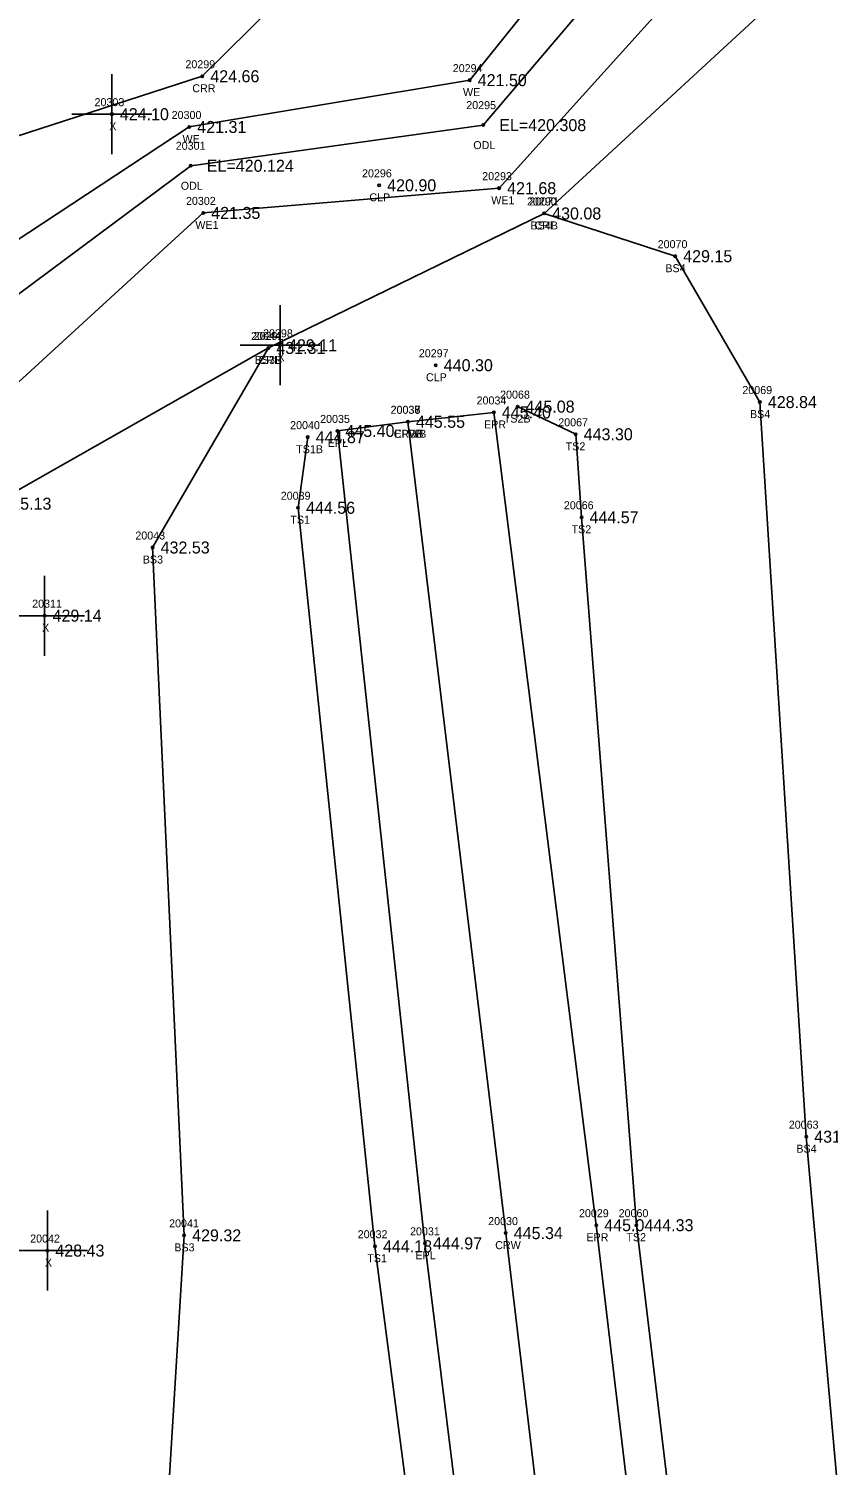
# Model space of a CAD drawing. Extents: x 1858461 to 1858936, y 1147060 to 1148183.
# Drawn here: x 1858641.9 to 1858741.9, y 1147440.4 to 1147619.9 of the extents above; entities that cross this region are included whole.
import ezdxf

# ---------------------------------------------------------------- set-up
doc = ezdxf.new("R2010")
doc.units = 0
for name, color, linetype in [('RD_DTM_BkLn1', 7, 'Continuous'), ('RD_DTM_BkLn2', 7, 'Continuous'), ('RD_DTM_BkLn_txCode', 7, 'Continuous'), ('RD_EX_H2O', 7, 'Continuous'), ('RD_EX_H2O_txCode', 7, 'Continuous'), ('RD_EX_Misc', 7, 'Continuous'), ('RD_EX_Misc_txCode', 7, 'Continuous'), ('RD_EX_Road', 7, 'Continuous'), ('RD_EX_Road_txCode', 7, 'Continuous'), ('RD_EX_TX_H2O_ELEV', 7, 'Continuous'), ('RD_EX_TX_Misc_ELEV', 7, 'Continuous'), ('RD_EX_TX_Road_ELEV', 7, 'Continuous'), ('RD_HC_Survey_ELEV', 7, 'Continuous'), ('RD_HC_Survey_txCode', 7, 'Continuous'), ('RD_SMD_Locator', 7, 'Continuous')]:
    doc.layers.add(name, color=color, linetype=linetype)

msp = doc.modelspace()

# ---------------------------------------------------------------- linework, layer by layer
at = {"layer": 'RD_DTM_BkLn1'}
msp.add_lwpolyline([(1858749.22, 1147073.22), (1858736.71, 1147171.73), (1858725.84, 1147271.15), (1858713.42, 1147369.59), (1858701.55, 1147469.39), (1858689.32, 1147570.79)], dxfattribs=at)
at = {"layer": 'RD_DTM_BkLn2'}
for points in [[(1858771.94, 1147076.95), (1858767.25, 1147173.88), (1858758.88, 1147274.75), (1858748.81, 1147373.06), (1858739.11, 1147481.44), (1858733.31, 1147573.26), (1858722.73, 1147591.49), (1858706.35, 1147596.83)], [(1858714.74, 1147067.6), (1858710.56, 1147167.02), (1858688.24, 1147264.23), (1858669.68, 1147349.51), (1858651.77, 1147379.27), (1858656.32, 1147386.54), (1858661.34, 1147469.11), (1858657.4, 1147555.08), (1858671.87, 1147580.02)], [(1858771.94, 1147076.95), (1858754.29, 1147172.99), (1858743.32, 1147272.09), (1858729.94, 1147370.14), (1858717.88, 1147470.38), (1858711.02, 1147558.86), (1858710.29, 1147569.23), (1858703.02, 1147572.69)], [(1858727.7, 1147071.22), (1858717.51, 1147168.6), (1858707.4, 1147267.83), (1858698.1, 1147368.78), (1858685.2, 1147467.75), (1858675.58, 1147560.05), (1858676.79, 1147568.87)]]:
    msp.add_lwpolyline(points, dxfattribs=at)
at = {"layer": 'RD_EX_H2O'}
for points in [[(1858879.83, 1148102.54), (1858871.42, 1148034.27), (1858866.93, 1147971.73), (1858863.21, 1147909.44), (1858860.9, 1147860.04), (1858873.82, 1147825.54), (1858891.79, 1147781.55), (1858894.95, 1147773.07), (1858887.01, 1147735.25), (1858825.08, 1147733.03), (1858791.14, 1147702.41), (1858765.02, 1147654.77), (1858740.99, 1147628.76), (1858706.35, 1147596.83), (1858671.87, 1147580.02), (1858637.61, 1147560.56), (1858613.46, 1147539.88), (1858609.2, 1147499), (1858608.26, 1147474.71), (1858583.43, 1147442.99), (1858542.68, 1147417.32), (1858497.34, 1147430.55)], [(1858719.03, 1147640.86), (1858697.04, 1147613.49), (1858661.98, 1147607.64), (1858625.4, 1147583.56), (1858593.78, 1147556.65), (1858579.85, 1147528.99), (1858580.76, 1147506.8), (1858583.29, 1147497.49), (1858586.38, 1147483.55), (1858572.3, 1147450.98), (1858541.76, 1147440.52), (1858492.95, 1147457.15)], [(1858724.58, 1147638.24), (1858698.73, 1147607.87), (1858662.17, 1147602.79), (1858628.85, 1147578), (1858598.27, 1147556.08), (1858583.61, 1147526.93), (1858588.64, 1147506.43), (1858594.87, 1147479.87), (1858576, 1147449.35), (1858543.69, 1147433.38), (1858490.97, 1147450.56)], [(1858731.96, 1147634.67), (1858700.72, 1147599.99), (1858663.73, 1147596.9), (1858633.09, 1147568.88), (1858613.78, 1147558.13), (1858600.73, 1147553.45), (1858596.93, 1147503.46), (1858602.13, 1147476.11), (1858578.57, 1147446.11), (1858546.06, 1147423.44), (1858491.42, 1147437.96)], [(1858681.73, 1147631.9), (1858663.61, 1147613.98), (1858627.73, 1147602.37), (1858587.46, 1147561.81), (1858570.79, 1147529.07), (1858577.35, 1147512.16), (1858564.18, 1147528.65), (1858536.5, 1147564.8), (1858503.8, 1147609.24)]]:
    msp.add_lwpolyline(points, dxfattribs=at)
at = {"layer": 'RD_EX_Misc'}
for p, q in [((1858652.3, 1147604.24), (1858652.3, 1147614.24)), ((1858647.3, 1147609.24), (1858657.3, 1147609.24)), ((1858673.33, 1147575.35), (1858673.33, 1147585.35)), ((1858668.33, 1147580.35), (1858678.33, 1147580.35)), ((1858643.89, 1147541.56), (1858643.89, 1147551.56)), ((1858638.89, 1147546.56), (1858648.89, 1147546.56)), ((1858644.24, 1147462.21), (1858644.24, 1147472.21)), ((1858639.24, 1147467.21), (1858649.24, 1147467.21))]:
    msp.add_line(p, q, dxfattribs=at)
at = {"layer": 'RD_EX_Road'}
for points in [[(1858760.33, 1147074.17), (1858747.61, 1147172.63), (1858736.08, 1147271.97), (1858724.51, 1147372.2), (1858712.86, 1147470.38), (1858700.06, 1147571.96), (1858689.32, 1147570.79)], [(1858739.58, 1147072.32), (1858726.74, 1147170.58), (1858715.7, 1147269.68), (1858703.76, 1147368.69), (1858691.45, 1147468.11), (1858680.5, 1147569.65), (1858689.32, 1147570.79)]]:
    msp.add_lwpolyline(points, dxfattribs=at)
at = {"layer": 'RD_SMD_Locator'}
for centre in [(1858663.61, 1147613.98), (1858697.04, 1147613.49), (1858652.3, 1147609.24), (1858661.98, 1147607.64), (1858698.73, 1147607.87), (1858662.17, 1147602.79), (1858685.72, 1147600.35), (1858700.72, 1147599.99), (1858663.73, 1147596.9), (1858706.35, 1147596.83), (1858706.35, 1147596.83), (1858722.73, 1147591.49), (1858673.33, 1147580.35), (1858671.87, 1147580.02), (1858671.87, 1147580.02), (1858692.8, 1147577.86), (1858733.31, 1147573.26), (1858700.06, 1147571.96), (1858703.02, 1147572.69), (1858680.5, 1147569.65), (1858689.32, 1147570.79), (1858689.32, 1147570.79), (1858689.32, 1147570.79), (1858676.79, 1147568.87), (1858710.29, 1147569.23), (1858675.58, 1147560.05), (1858711.02, 1147558.86), (1858657.4, 1147555.08), (1858643.89, 1147546.56), (1858739.11, 1147481.44), (1858661.34, 1147469.11), (1858701.55, 1147469.39), (1858712.86, 1147470.38), (1858717.88, 1147470.38), (1858644.24, 1147467.21), (1858685.2, 1147467.75), (1858691.45, 1147468.11)]:
    msp.add_circle(centre, 0.15, dxfattribs=at)

# ---------------------------------------------------------------- texts
at = {"layer": 'RD_DTM_BkLn_txCode'}
for s, p in [('20071', (1858704.48, 1147597.83)), ('BS4B', (1858704.65, 1147594.83)), ('20070', (1858720.54, 1147592.49)), ('BS4', (1858721.5, 1147589.49)), ('20044', (1858669.71, 1147581.02)), ('BS3B', (1858670.17, 1147578.02)), ('20069', (1858731.13, 1147574.26)), ('20068', (1858700.84, 1147573.69)), ('TS2B', (1858701.3, 1147570.69)), ('BS4', (1858732.08, 1147571.26)), ('20040', (1858674.59, 1147569.87)), ('20067', (1858708.11, 1147570.23)), ('TS2', (1858709.04, 1147567.23)), ('TS1B', (1858675.35, 1147566.87)), ('20039', (1858673.42, 1147561.05)), ('20066', (1858708.81, 1147559.86)), ('TS1', (1858674.62, 1147558.05)), ('TS2', (1858709.78, 1147556.86)), ('20043', (1858655.24, 1147556.08)), ('BS3', (1858656.17, 1147553.08)), ('20063', (1858736.93, 1147482.44)), ('BS4', (1858737.88, 1147479.44)), ('20041', (1858659.46, 1147470.11)), ('20060', (1858715.66, 1147471.38)), ('20032', (1858683.04, 1147468.75)), ('TS2', (1858716.63, 1147468.38)), ('BS3', (1858660.11, 1147467.11)), ('TS1', (1858684.24, 1147465.75))]:
    msp.add_text(s, height=1, dxfattribs=at).set_placement(p)
at = {"layer": 'RD_EX_H2O_txCode'}
for s, p in [('20299', (1858661.5, 1147614.98)), ('20294', (1858694.92, 1147614.49)), ('CRR', (1858662.36, 1147611.98)), ('WE', (1858696.2, 1147611.49)), ('20300', (1858659.78, 1147608.64)), ('20295', (1858696.61, 1147609.87)), ('20301', (1858660.29, 1147604.79)), ('WE', (1858661.14, 1147605.64)), ('ODL', (1858697.49, 1147604.87)), ('ODL', (1858660.92, 1147599.79)), ('20293', (1858698.6, 1147600.99)), ('20302', (1858661.57, 1147597.9)), ('WE1', (1858699.73, 1147597.99)), ('20290', (1858704.2, 1147597.83)), ('WE1', (1858662.74, 1147594.9)), ('CRL', (1858705.13, 1147594.83)), ('20291', (1858670.03, 1147581.02)), ('CRL', (1858670.64, 1147578.02))]:
    msp.add_text(s, height=1, dxfattribs=at).set_placement(p)
at = {"layer": 'RD_EX_Misc_txCode'}
for s, p in [('20303', (1858650.14, 1147610.24)), ('X', (1858651.98, 1147607.24)), ('20298', (1858671.21, 1147581.35)), ('X', (1858673.01, 1147578.35)), ('20311', (1858642.34, 1147547.56)), ('X', (1858643.58, 1147544.56)), ('20042', (1858642.09, 1147468.21)), ('X', (1858643.93, 1147465.21))]:
    msp.add_text(s, height=1, dxfattribs=at).set_placement(p)
at = {"layer": 'RD_EX_Road_txCode'}
for s, p in [('20034', (1858697.9, 1147572.96)), ('20035', (1858678.34, 1147570.65)), ('20036', (1858687.14, 1147571.79)), ('20038', (1858687.16, 1147571.79)), ('EPRB', (1858687.62, 1147568.79)), ('EPLB', (1858687.64, 1147568.79)), ('EPR', (1858698.83, 1147569.96)), ('EPL', (1858679.29, 1147567.65)), ('20029', (1858710.7, 1147471.38)), ('20031', (1858689.58, 1147469.11)), ('EPR', (1858711.63, 1147468.38)), ('EPL', (1858690.25, 1147466.11))]:
    msp.add_text(s, height=1, dxfattribs=at).set_placement(p)
at = {"layer": 'RD_EX_TX_H2O_ELEV'}
for s, p in [('424.66', (1858664.61, 1147613.23)), ('421.50', (1858698.04, 1147612.74)), ('421.31', (1858662.98, 1147606.89)), ('EL=420.308', (1858700.73, 1147607.12)), ('EL=420.124', (1858664.17, 1147602.04)), ('421.68', (1858701.72, 1147599.24)), ('421.35', (1858664.73, 1147596.15)), ('430.08', (1858707.35, 1147596.08)), ('431.31', (1858672.87, 1147579.27)), ('425.13', (1858638.61, 1147559.81))]:
    msp.add_text(s, height=1.5, dxfattribs=at).set_placement(p)
at = {"layer": 'RD_EX_TX_Misc_ELEV'}
for s, p in [('424.10', (1858653.3, 1147608.49)), ('430.08', (1858707.35, 1147596.08)), ('429.15', (1858723.73, 1147590.74)), ('431.31', (1858672.87, 1147579.27)), ('429.11', (1858674.33, 1147579.6)), ('445.08', (1858704.02, 1147571.94)), ('428.84', (1858734.31, 1147572.51)), ('443.30', (1858711.29, 1147568.48)), ('444.87', (1858677.79, 1147568.12)), ('444.56', (1858676.58, 1147559.3)), ('444.57', (1858712.02, 1147558.11)), ('432.53', (1858658.4, 1147554.33)), ('429.14', (1858644.89, 1147545.81)), ('431.40', (1858740.11, 1147480.69)), ('444.33', (1858718.88, 1147469.63)), ('429.32', (1858662.34, 1147468.36)), ('428.43', (1858645.24, 1147466.46)), ('444.18', (1858686.2, 1147467))]:
    msp.add_text(s, height=1.5, dxfattribs=at).set_placement(p)
at = {"layer": 'RD_EX_TX_Road_ELEV'}
for s, p in [('445.55', (1858690.32, 1147570.04)), ('445.55', (1858690.32, 1147570.04)), ('445.40', (1858701.06, 1147571.21)), ('445.40', (1858681.5, 1147568.9)), ('445.04', (1858713.86, 1147469.63)), ('444.97', (1858692.45, 1147467.36))]:
    msp.add_text(s, height=1.5, dxfattribs=at).set_placement(p)
at = {"layer": 'RD_HC_Survey_ELEV'}
for s, p in [('420.90', (1858686.72, 1147599.6)), ('440.30', (1858693.8, 1147577.11)), ('445.55', (1858690.32, 1147570.04)), ('445.34', (1858702.55, 1147468.64))]:
    msp.add_text(s, height=1.5, dxfattribs=at).set_placement(p)
at = {"layer": 'RD_HC_Survey_txCode'}
for s, p in [('20296', (1858683.58, 1147601.35)), ('CLP', (1858684.49, 1147598.35)), ('20297', (1858690.68, 1147578.86)), ('CLP', (1858691.57, 1147575.86)), ('20037', (1858687.16, 1147571.79)), ('CRWB', (1858687.53, 1147568.79)), ('20030', (1858699.35, 1147470.39)), ('CRW', (1858700.23, 1147467.39))]:
    msp.add_text(s, height=1, dxfattribs=at).set_placement(p)

doc.saveas('drawing.dxf')
